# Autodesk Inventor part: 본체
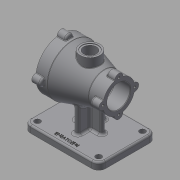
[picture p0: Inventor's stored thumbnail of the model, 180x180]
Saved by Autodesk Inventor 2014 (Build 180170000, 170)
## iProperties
Created: 2020-12
Part Number: 본체
Material: Generic
Document SubType Name: Modeling
Designer: kh
Density: 1 g/cm^3
Appearance: Default
Mass: 382.358 g
Surface Area: 851.644 cm^2
Volume: 382.358 cm^3
Author: kh
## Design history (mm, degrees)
sketch "스케치1"
  geometry: L1 (-65, -50)-(65, -50); L2 (65, -50)-(65, 50); L3 (65, 50)-(-65, 50); L4 (-65, 50)-(-65, -50); L5 (-65, -50)-(65, 50); L6 (65, -50)-(-65, 50); 1 further point
  constraints: 12 end point, 2 midpoint, 2 parallel, 1 horizontal, 1 perpendicular
  dimensions: "d0" = 130 distance of L2.end L3.end; "d1" = 100 distance of L1.end L2.end
extrude "돌출1" new body sketch "스케치1" distance "d2" = 12; taper "d3" = 0 deg
fillet "모깎기1" dims "d4" = 12
hole "구멍1" diameter "d7" = 10; stored, may be unused: countersink angle "d11" = 90 deg, drill point angle "d13" = 118 deg; dims "d5" = 10, "d6" = 10, "d8" = 6, "d9" = 4, "d10" = 2, "d12" = 8
sketch "스케치2"
  geometry: L1 (-50, 82)-(50, 82); L2 (-50, 82)-(-50, 126); L3 (-50, 126)-(-30, 126); L4 (-30, 126)-(25, 109.5); L5 (25, 109.5)-(50, 109.5); L6 (50, 109.5)-(50, 82); L7 (53, 0)-(-53, 0) reference; 3 further points
  constraints: 12 end point, 2 midpoint, 2 parallel, 2 perpendicular, 1 horizontal, 1 vertical alignment
  dimensions: "d18" = 88 diameter of L3 L1; "d19" = 82 distance between parallel lines of L7 L1; "d20" = 55 diameter of L5 L1; "d21" = 100 distance between parallel lines of L6 L2; "d23" = 20 horizontal distance of L3.end L1.start; "d133" = 25 distance from line of L4.end L6
revolve "회전1" sketch "스케치2" stored, may be unused: angle "d22" = 90 deg
node "작업 평면2"
node "작업 평면3"
hole "구멍2" diameter "d39" = 64; stored, may be unused: countersink angle "d43" = 90 deg, drill point angle "d45" = 0 deg; dims "d37" = 10, "d38" = 10, "d40" = 6, "d41" = 4, "d42" = 2, "d44" = 23
hole "구멍3" diameter "d48" = 52; stored, may be unused: countersink angle "d52" = 90 deg, drill point angle "d54" = 0 deg; dims "d46" = 10, "d47" = 10, "d49" = 6, "d50" = 4, "d51" = 2, "d53" = 47
hole "구멍4" diameter "d57" = 40; stored, may be unused: countersink angle "d61" = 90 deg, drill point angle "d63" = 0 deg; dims "d55" = 10, "d56" = 10, "d58" = 6, "d59" = 4, "d60" = 2, "d62" = 30
sketch "스케치9"
  geometry: C1 r 20 at (0, 0) reference; C2 r 7 at (0, 27.5); 2 further points
  constraints: 2 vertical alignment, 1 centre point, 1 other
  dimensions: "d65" = 7 radius of C2
extrude "돌출4" join sketch "스케치9" distance "d66" = 15; taper "d67" = 0 deg
sketch "스케치10"
  geometry: C1 r 32 at (0, 0) reference; C2 r 7 at (-44, 0); 2 further points
  constraints: 2 horizontal alignment, 1 centre point, 1 other
  dimensions: "d71" = 7 radius of C2
extrude "돌출5" join sketch "스케치10" distance "d72" = 15; taper "d73" = 0 deg
hole "구멍5" diameter "d79" = 4.134; stored, may be unused: countersink angle "d83" = 90 deg, drill point angle "d85" = 118 deg; dims "d77" = 10, "d78" = 10, "d80" = 9, "d81" = 4, "d82" = 2, "d84" = 11
hole "구멍6" diameter "d91" = 4.134; stored, may be unused: countersink angle "d95" = 90 deg, drill point angle "d97" = 118 deg; dims "d89" = 10, "d90" = 10, "d92" = 9, "d93" = 4, "d94" = 2, "d96" = 11
node "작업 평면4"
sketch "스케치11"
  geometry: C1 r 17 at (0, 0); 1 further point
  constraints: 1 centre point, 1 coincident
  dimensions: "d102" = 34 diameter of C1
extrude "돌출6" join sketch "스케치11" stored distance "d103" = 15; taper "d104" = 0 deg
hole "구멍7" diameter "d107" = 22; stored, may be unused: countersink angle "d111" = 90 deg, drill point angle "d113" = 0 deg; dims "d105" = 10, "d106" = 10, "d108" = 9, "d109" = 28, "d110" = 1, "d112" = 27.25
fillet "모깎기2" dims "d114" = 3
fillet "모깎기3" dims "d115" = 3
fillet "모깎기4" dims "d116" = 1
fillet "모깎기5" dims "d120" = 3
fillet "모깎기6" dims "d121" = 1
fillet "모깎기8" dims "d126" = 3
chamfer "모따기1" distance "d127" = 1; stored, may be unused: second distance "d128" = 2, angle "d129" = 45 deg
fillet "모깎기9" dims "d130" = 1
fillet "모깎기10" dims "d131" = 3
sketch "스케치12"
  geometry: L1 (4, 25)-(-4, 25); L2 (-4, 25)-(-4, -25); L3 (-4, -25)-(4, -25); L4 (4, -25)-(4, 25); L5 (4, 25)-(-4, -25); L6 (-4, 25)-(4, -25); 2 further points
  constraints: 12 end point, 3 midpoint, 2 parallel, 1 horizontal, 1 perpendicular
  dimensions: "d134" = 8 distance of L3.end L2.end; "d135" = 50 distance between parallel lines of L1 L3
extrude "돌출7" join sketch "스케치12" stored distance "d136" = 15; taper "d137" = 0 deg
sketch "스케치13"
  geometry: L1 (24, 4)-(-24, 4); L2 (-24, 4)-(-24, -4); L3 (-24, -4)-(24, -4); L4 (24, -4)-(24, 4); L5 (24, 4)-(-24, -4); L6 (-24, 4)-(24, -4); 1 further point
  constraints: 12 end point, 2 midpoint, 2 parallel, 1 horizontal, 1 perpendicular
  dimensions: "d138" = 48 distance between parallel lines of L2 L4; "d139" = 8 distance between parallel lines of L1 L3
extrude "돌출8" join sketch "스케치13" stored distance "d140" = 15; taper "d141" = 0 deg
fillet "모깎기12" dims "d142" = 4
fillet "모깎기13" dims "d143" = 4
sketch "스케치14"
  geometry: L1 (53, 50)-(-53, 50) reference; 2 further points
  constraints: 1 vertical alignment, 1 other
  dimensions: "d144" = 10 distance from line of point (0, 40) L1
feature "엠보싱1" sketch "스케치14" dims "d145" = 0.5, "d146" = 0
fillet "모깎기14" dims "d147" = 3
node "솔리드1"
pattern_linear "직사각형 패턴1"
pattern_circular "원형 패턴1" dims angle "d69" = 360 deg
pattern_circular "원형 패턴2" dims angle "d75" = 360 deg
pattern_circular "원형 패턴3" dims angle "d87" = 360 deg
pattern_circular "원형 패턴4" dims angle "d99" = 360 deg
pattern_circular "원형 패턴5" dims angle "d118" = 360 deg
pattern_circular "원형 패턴6" dims angle "d123" = 360 deg
other parameters: "d101" = 127
